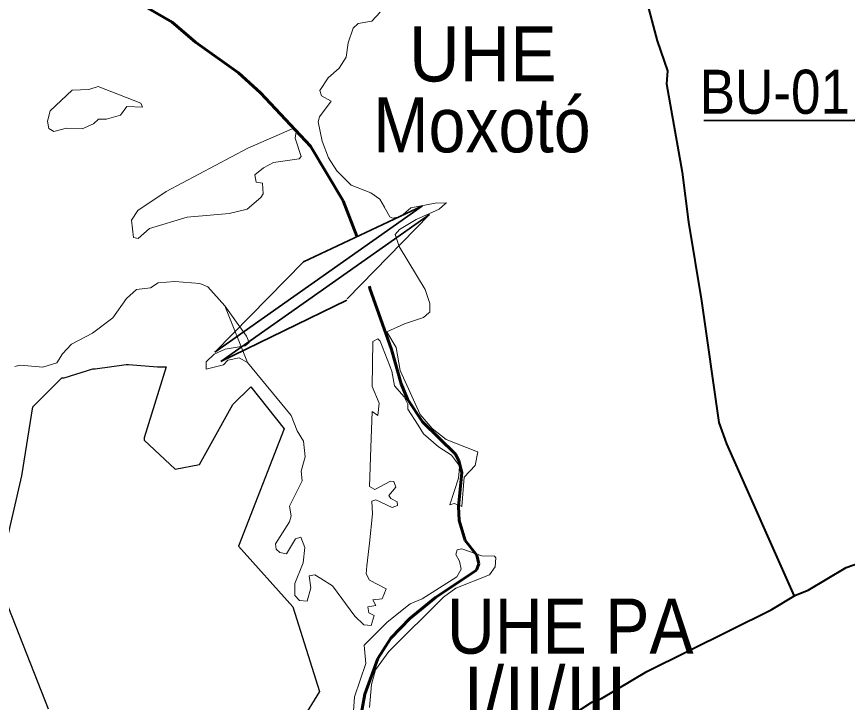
# Model space of a CAD drawing. Extents: x 553962 to 842807, y 8883888 to 9032388.
# Drawn here: x 584337 to 591881, y 8960263 to 8966488 of the extents above; entities that cross this region are included whole.
import ezdxf
from ezdxf.enums import TextEntityAlignment as Align

# ---------------------------------------------------------------- set-up
doc = ezdxf.new("R2010")
doc.units = 0
doc.header["$LTSCALE"] = 150
doc.linetypes.add('LONG_DASH_SHORT_DASH', pattern=[9.9, 6, -1.2, 1.5, -1.2])
for name, color, linetype, lineweight in [('12', 7, 'Continuous', 25), ('21', 7, 'Continuous', 25), ('25', 7, 'Continuous', 13), ('40', 7, 'Continuous', 60), ('7', 7, 'LONG_DASH_SHORT_DASH', 60)]:
    doc.layers.add(name, color=color, linetype=linetype, lineweight=lineweight)
doc.layers.add('42', color=7, linetype='Continuous')

msp = doc.modelspace()

# ---------------------------------------------------------------- linework, layer by layer
at = {"layer": '12', "lineweight": 40}
for points in [[(587301, 8972874.3), (587640.4, 8972251.7), (587788.5, 8972042.4), (588207.4, 8971376.7), (588263.1, 8971248.8), (588483.5, 8970850.8), (588695.4, 8970396.6), (588857.5, 8969895.4), (589190.3, 8968987.7), (589251, 8968710.7), (589674.6, 8967582.3), (589899.5, 8967058.9), (590052.2, 8966645.4), (590154.6, 8966267.7), (590247.4, 8965995.5), (590238.8, 8965878.8), (590381.4, 8965077.2), (590437.7, 8964620.9), (590556.9, 8963909.5), (590712.3, 8962804.7), (590781.8, 8962609.4), (591396.4, 8961227.9)], [(587134, 8956453.8), (587843.6, 8957685.7), (587923.7, 8957988.5), (588169.9, 8958625.1), (588237, 8958904.7), (588304.1, 8959099.5), (588468, 8959448.9), (588578.9, 8959635.8), (588673.7, 8959750.1), (588777.5, 8959843.1), (589203.6, 8960089.7), (589393.4, 8960175.8), (589428.5, 8960178.5), (589560.1, 8960264.6), (589648.9, 8960297.2), (590059.4, 8960543.5), (591188.1, 8961101.4), (591408.7, 8961235.4), (591525.3, 8961280.9), (591868.7, 8961488.1), (592154.1, 8961587.2), (592311.1, 8961655)]]:
    msp.add_lwpolyline(points, dxfattribs=at)
at = {"layer": '21'}
msp.add_lwpolyline([(584626.8, 8960201.4), (584162.8, 8961372.1), (584384.7, 8962320.7), (584485.6, 8962946.4), (584747.9, 8963208.8), (584768.1, 8963208.8), (585030.4, 8963289.5), (585050.6, 8963289.5), (585333, 8963329.9), (585353.2, 8963329.9), (585615.5, 8963309.7), (585655.9, 8963309.7), (585676, 8963309.7), (585696.2, 8963309.7), (585494.5, 8962663.8), (585494.5, 8962643.7), (585776.9, 8962381.3), (585998.9, 8962421.6), (586301.5, 8962966.6), (586463, 8963128.1), (586765.6, 8962744.6), (586351.3, 8961682.2), (586846.3, 8961129.9), (587088.5, 8960362.9), (586927, 8960100.5)], dxfattribs=at)
at = {"layer": '25', "lineweight": 35}
for p, q in [((588022.6, 8964770.6), (586135.6, 8963442.6)), ((586940.7, 8964263.4), (588022.6, 8964770.6)), ((588084.7, 8964692), (586189.9, 8963358.5)), ((587339.3, 8963925.5), (588084.7, 8964692)), ((586940.7, 8964263.4), (586135.6, 8963442.6)), ((586189.9, 8963358.5), (587335.7, 8963913.8))]:
    msp.add_line(p, q, dxfattribs=at)
at = {"layer": '25'}
for points in [[(587637.4, 8966529.4), (587563.2, 8966446.7), (587438, 8966427.4), (587392.7, 8966384.2), (587348.6, 8966249.6), (587329.2, 8966121.3), (587265.6, 8966019.6), (587165.8, 8965932.5), (587089.5, 8965818), (587106.5, 8965769), (587193.3, 8965719.9), (587087.2, 8965577.5), (587074.5, 8965534.6), (587110.7, 8965356.6), (587170.4, 8965207.5), (587244.3, 8965087.2), (587376.1, 8964957.5), (587554.3, 8964887.4), (587635.2, 8964832.1), (587726.7, 8964670.8), (587750.6, 8964658), (587826.4, 8964675), (587917.9, 8964751.3), (588138.8, 8964796.3), (588239.8, 8964798.6), (588239.8, 8964798.6), (588231, 8964790.9)], [(587637.4, 8966529.4), (587563.2, 8966446.7), (587438, 8966427.4), (587392.7, 8966384.2), (587348.6, 8966249.6), (587329.2, 8966121.3), (587265.6, 8966019.6), (587165.8, 8965932.5), (587089.5, 8965818), (587106.5, 8965769), (587193.3, 8965719.9), (587087.2, 8965577.5), (587074.5, 8965534.6), (587110.7, 8965356.6), (587170.4, 8965207.5), (587244.3, 8965087.2), (587376.1, 8964957.5), (587554.3, 8964887.4), (587635.2, 8964832.1), (587678.5, 8964757.6)], [(588231, 8964790.9), (588174.2, 8964740.5), (587964.7, 8964647.4), (587813.9, 8964556), (587773.6, 8964509.6), (587809.5, 8964400.9), (588045.3, 8964009.8), (588090.5, 8963883.4), (588087.9, 8963805.8), (588079.5, 8963798.7)], [(587773.6, 8964509.6), (587809.5, 8964400.9), (588045.3, 8964009.8), (588090.5, 8963883.4), (588087.9, 8963805.8), (588079.5, 8963798.7)], [(587098.4, 8961386.8), (587045, 8961420.4), (586993.8, 8961411.8), (587008.6, 8961303.5), (586976.2, 8961182.7), (586906.7, 8961189.1), (586864.3, 8961233.5), (586864.2, 8961341.7), (586938.6, 8961529.2), (586953.1, 8961669.7), (586916.8, 8961762.6), (586868.3, 8961747.5), (586787.2, 8961611.7), (586725.9, 8961622.5), (586694.3, 8961654.3), (586687.9, 8961700.7), (586815.2, 8961902.8), (586830.2, 8961956.5), (586815.4, 8962043.2), (586930, 8962273.3), (586921.5, 8962361.5), (586957.6, 8962493.3), (586943, 8962632.7), (586885.4, 8962727), (586830, 8962867.4), (586432.9, 8963349.4), (586358.6, 8963389.7), (586254.6, 8963368.5), (586216.2, 8963326.1), (586059.1, 8963288.1), (586058.9, 8963353.2), (586131.1, 8963423.6), (586229.2, 8963469.6), (586410.8, 8963500), (586449.8, 8963530), (586424.4, 8963587.3), (586226.9, 8963861.3), (586073.9, 8964035.5), (585999.3, 8964065.2), (585774.7, 8964084.4), (585623.6, 8964071.6), (585553.5, 8964025), (585426.1, 8964010), (585334.9, 8963929.5), (585211.3, 8963752.8), (585026.9, 8963615.1), (584835.5, 8963515.1), (584755, 8963428.2), (584703.5, 8963345.2), (584575.7, 8963306.9), (584575.7, 8963306.9), (584367.9, 8963323.8), (584319.4, 8963311.1)], [(587098.4, 8961386.8), (587045, 8961420.4), (586993.8, 8961411.8), (587008.6, 8961303.5), (586976.2, 8961182.7), (586906.7, 8961189.1), (586864.3, 8961233.5), (586864.2, 8961341.7), (586938.6, 8961529.2), (586953.1, 8961669.7), (586916.8, 8961762.6), (586868.3, 8961747.5), (586787.2, 8961611.7), (586725.9, 8961622.5), (586694.3, 8961654.3), (586687.9, 8961700.7), (586815.2, 8961902.8), (586830.2, 8961956.5), (586815.4, 8962043.2), (586930, 8962273.3), (586921.5, 8962361.5), (586957.6, 8962493.3), (586943, 8962632.7), (586885.4, 8962727), (586830, 8962867.4), (586432.9, 8963349.4), (586226.9, 8963861.3), (586073.9, 8964035.5), (585999.3, 8964065.2), (585774.7, 8964084.4), (585623.6, 8964071.6), (585553.5, 8964025), (585426.1, 8964010), (585334.9, 8963929.5), (585211.3, 8963752.8), (585026.9, 8963615.1), (584835.5, 8963515.1), (584755, 8963428.2), (584703.5, 8963345.2), (584575.7, 8963306.9), (584575.7, 8963306.9), (584367.9, 8963323.8), (584319.4, 8963311.1)], [(588079.5, 8963798.7), (588030.2, 8963757.2), (587858.5, 8963700), (587699.1, 8963625.3), (587781.9, 8963483), (587820, 8963275.3), (588002, 8962877.1), (588002, 8962877.1), (588108.8, 8962750.5), (588236.2, 8962650.7), (588523, 8962536.8)], [(588079.5, 8963798.7), (588030.2, 8963757.2), (587858.5, 8963700), (587699.1, 8963625.3), (587781.9, 8963483), (587820, 8963275.3), (588002, 8962877.1), (588002, 8962877.1), (588108.8, 8962750.5), (588236.2, 8962650.7), (588523, 8962536.8)], [(587982.8, 8962779.3), (587890.3, 8962924.4), (587890.1, 8962969.1), (587856.3, 8963036.9), (587766.9, 8963135.1), (587743.6, 8963270.8), (587637.1, 8963543.2), (587617, 8963563.8), (587571.7, 8963538.4), (587565.1, 8963131.3), (587628.8, 8962977.9), (587616.1, 8962866.9), (587565.4, 8962902.1), (587554.1, 8962576.4)], [(587982.8, 8962779.3), (587890.3, 8962924.4), (587890.1, 8962969.1), (587856.3, 8963036.9), (587766.9, 8963135.1), (587743.6, 8963270.8), (587637.1, 8963543.2), (587617, 8963563.8), (587571.7, 8963538.4), (587565.1, 8963131.3), (587628.8, 8962977.9), (587616.1, 8962866.9), (587565.4, 8962902.1), (587554.1, 8962576.4)], [(588354.5, 8962361.1), (588359.4, 8962408.8), (588285.5, 8962505.9), (588167, 8962584.2), (588032.3, 8962701.8), (587982.8, 8962779.3)], [(588354.5, 8962361.1), (588359.4, 8962408.8), (588285.5, 8962505.9), (588167, 8962584.2), (588032.3, 8962701.8), (587982.8, 8962779.3)], [(587554.1, 8962576.4), (587541.8, 8962223.9), (587588.7, 8962196), (587730.7, 8962272.2), (587762.7, 8962269), (587781.7, 8962215.1)], [(587554.1, 8962576.4), (587541.8, 8962223.9), (587588.7, 8962196), (587730.7, 8962272.2), (587762.7, 8962269), (587781.7, 8962215.1)], [(588523, 8962536.8), (588524.4, 8962536.2), (588501.9, 8962412.8), (588402.2, 8962308.3), (588381.1, 8962040.8), (588376.4, 8962042.8)], [(588523, 8962536.8), (588524.4, 8962536.2), (588501.9, 8962412.8), (588402.2, 8962308.3), (588381.1, 8962040.8), (588376.4, 8962042.8)], [(588271.6, 8962055.8), (588270.1, 8962055.2), (588348.1, 8962299.3), (588354.5, 8962361.1)], [(588271.6, 8962055.8), (588270.1, 8962055.2), (588348.1, 8962299.3), (588354.5, 8962361.1)], [(587781.7, 8962215.1), (587781.7, 8962215.1), (587718.2, 8962140.9), (587735, 8962113.3), (587792.4, 8962083.3), (587794.6, 8962050), (587745.5, 8962032.4), (587597.2, 8962100.2), (587563.1, 8962089.5), (587569.5, 8961975.7), (587540.2, 8961707.3), (587517.7, 8961501.6)], [(587781.7, 8962215.1), (587781.7, 8962215.1), (587718.2, 8962140.9), (587735, 8962113.3), (587792.4, 8962083.3), (587794.6, 8962050), (587745.5, 8962032.4), (587597.2, 8962100.2), (587563.1, 8962089.5), (587569.5, 8961975.7), (587540.2, 8961707.3), (587517.7, 8961501.6)], [(588376.4, 8962042.8), (588311.2, 8962069.4), (588271.6, 8962055.8), (588271.7, 8962060.3), (588271.6, 8962055.8)], [(588376.4, 8962042.8), (588311.2, 8962069.4), (588271.6, 8962055.8), (588271.7, 8962060.3), (588271.6, 8962055.8)], [(587541.6, 8960215), (587558.8, 8960425), (587596.7, 8960558.6), (587717.4, 8960723.2), (588213.5, 8961217.2), (588323.7, 8961300.9), (588630.6, 8961421.7), (588681.9, 8961493.8), (588689.2, 8961575.7), (588675.2, 8961590.7), (588561, 8961592.8), (588381.1, 8961656.2), (588338.6, 8961648.6), (588325.4, 8961606.6), (588359, 8961544.8), (588373.9, 8961471.3), (588335.7, 8961403.9), (588018, 8961201.6), (587911.6, 8961156.7), (587701, 8960992.4), (587493.3, 8960783.2), (587506.9, 8960616.2), (587403.7, 8960314.5), (587373.8, 8959887.7)], [(587517.7, 8961501.6), (587510, 8961431.2), (587539.9, 8961371.6), (587692.7, 8961292.6), (587670.8, 8961239.2)], [(587517.7, 8961501.6), (587510, 8961431.2), (587539.9, 8961371.6), (587692.7, 8961292.6), (587670.8, 8961239.2)], [(587670.8, 8961239.2), (587656.4, 8961204.1), (587570.6, 8961194.6), (587599.2, 8961141.8), (587527.1, 8961129.4), (587535.4, 8961074.6), (587582.5, 8961050.1), (587556.1, 8960961.2), (587491.1, 8960968.1), (587408.1, 8961044.4), (587205.3, 8961319.5), (587098.4, 8961386.8)], [(587670.8, 8961239.2), (587656.4, 8961204.1), (587570.6, 8961194.6), (587599.2, 8961141.8), (587527.1, 8961129.4), (587535.4, 8961074.6), (587582.5, 8961050.1), (587556.1, 8960961.2), (587491.1, 8960968.1), (587408.1, 8961044.4), (587205.3, 8961319.5), (587098.4, 8961386.8)]]:
    msp.add_lwpolyline(points, dxfattribs=at)
for points in [[(585077.7, 8965854), (584992.7, 8965826.3), (584839.9, 8965820.3), (584642.3, 8965632.9), (584616.8, 8965540.1), (584629.5, 8965471.6), (584675.9, 8965446), (584789, 8965475.7), (584933.4, 8965469.6), (585035.3, 8965516.3), (585079.8, 8965558.5), (585154.1, 8965558.7), (585279.1, 8965592.6), (585337.4, 8965673.5), (585478.9, 8965666.9), (585463.8, 8965703.2)], [(585077.7, 8965854), (584992.7, 8965826.3), (584839.9, 8965820.3), (584642.3, 8965632.9), (584616.8, 8965540.1), (584629.5, 8965471.6), (584675.9, 8965446), (584789, 8965475.7), (584933.4, 8965469.6), (585035.3, 8965516.3), (585079.8, 8965558.5), (585154.1, 8965558.7), (585279.1, 8965592.6), (585337.4, 8965673.5), (585478.9, 8965666.9), (585463.8, 8965703.2)], [(585439, 8964728.2), (585379.4, 8964639), (585398.5, 8964484), (585440.9, 8964473.3), (585545, 8964564.5), (585884.6, 8964666.3), (586267.5, 8964700.5), (586430.8, 8964740.8), (586553.9, 8964845), (586575.2, 8964881), (586570.7, 8964976.5), (586513.6, 8964985.3), (586501.3, 8965053.3), (586579.7, 8965116.9), (586670.6, 8965163.4), (586903.9, 8965197.4), (586919.2, 8965218.6), (586866.7, 8965384.8), (586876.8, 8965441.6), (586860, 8965477.5), (586435.1, 8965293.1), (585696.3, 8964900.4)], [(585439, 8964728.2), (585379.4, 8964639), (585398.5, 8964484), (585440.9, 8964473.3), (585545, 8964564.5), (585884.6, 8964666.3), (586267.5, 8964700.5), (586430.8, 8964740.8), (586553.9, 8964845), (586575.2, 8964881), (586570.7, 8964976.5), (586513.6, 8964985.3), (586501.3, 8965053.3), (586579.7, 8965116.9), (586670.6, 8965163.4), (586903.9, 8965197.4), (586919.2, 8965218.6), (586866.7, 8965384.8), (586876.8, 8965441.6), (586860, 8965477.5), (586435.1, 8965293.1), (585696.3, 8964900.4)]]:
    msp.add_lwpolyline(points, close=True, dxfattribs=at)
at = {"layer": '40', "lineweight": 35}
msp.add_lwpolyline([(592338, 8965874), (591946.5, 8965544.8), (590577.5, 8965544.8)], dxfattribs=at)
at = {"layer": '7'}
for points in [[(583174.4, 8969966), (583327.9, 8969505.4), (583474.7, 8969160.4), (583725.5, 8968684.8), (583883.2, 8968539.9), (583982.9, 8968403.5), (584146.9, 8968235.1), (584624.8, 8967616.6), (584992.2, 8967072.1), (585186.8, 8966825.7), (585377.2, 8966655.9), (585748.8, 8966438.6), (585960.5, 8966257.3), (586351.6, 8965976.8), (586551, 8965796.4), (587006.6, 8965310.9), (587303.1, 8964815.2), (587426.7, 8964495.3)], [(587540.9, 8964040.5), (587545.5, 8964019), (587739.9, 8963466), (587828.5, 8963155), (587886.8, 8963016.8), (588023, 8962809.1), (588321.3, 8962515.1), (588353.7, 8962454.8), (588379.7, 8962350), (588349.5, 8962039.7), (588356.1, 8961913.4), (588409.9, 8961732.7), (588515.9, 8961598.5), (588533, 8961520.2), (588511.4, 8961464.3), (588140, 8961216), (587908.2, 8961023.1), (587733.4, 8960846.2), (587616.5, 8960660), (587498.3, 8960337.4), (587362.2, 8959603), (587314, 8959147.2), (587303.2, 8958935.8), (587310.7, 8958873)]]:
    msp.add_lwpolyline(points, dxfattribs=at)

# ---------------------------------------------------------------- texts
at = {"layer": '40', "width": 0.9}
msp.add_text('BU-01', height=400, dxfattribs=at).set_placement((590539.4, 8965606.1))
at = {"layer": '42'}
for s, width, p in [('UHE', 0.95, (588571.1, 8965899.4)), ('Moxotó', 0.9, (588562.6, 8965256.2)), ('UHE PA', 0.9, (589364.5, 8960705))]:
    msp.add_text(s, height=500, dxfattribs=dict(at, width=width)).set_placement(p, align=Align.CENTER)
msp.add_text('I/II/III', height=500, dxfattribs=at).set_placement((589134.4, 8960086.2), align=Align.CENTER)

doc.saveas('drawing.dxf')
